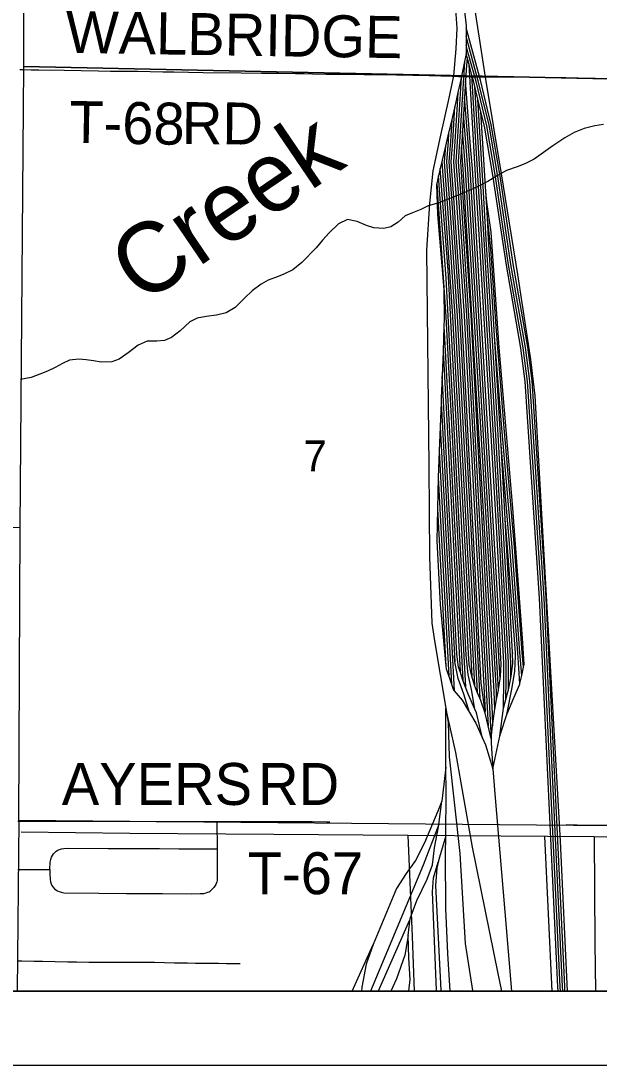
# Model space of a CAD drawing. Extents: x 0 to 40.2, y 0 to 22.
# Drawn here: x 2.953 to 3.735, y 14 to 15.414 of the extents above; entities that cross this region are included whole.
import ezdxf

# ---------------------------------------------------------------- set-up
doc = ezdxf.new("R2010")
doc.units = 0
for name, color, linetype in [('GM_X_Adjacent_County', 7, 'Continuous'), ('GM_X_City_Street', 7, 'Continuous'), ('GM_X_Corporation', 7, 'Continuous'), ('GM_X_County_Road_Text', 7, 'Continuous'), ('GM_X_Major_River', 7, 'Continuous'), ('GM_X_Minor_Lake', 7, 'Continuous'), ('GM_X_Minor_River', 7, 'Continuous'), ('GM_X_Rail_Line', 7, 'Continuous'), ('GM_X_Township_Road', 7, 'Continuous')]:
    doc.layers.add(name, color=color, linetype=linetype)

msp = doc.modelspace()

# ---------------------------------------------------------------- linework, layer by layer
at = {"layer": 'GM_X_Adjacent_County'}
for p, q in [((2.1, 14.1), (8.9, 14.1)), ((2, 14), (9, 14))]:
    msp.add_line(p, q, dxfattribs=at)
at = {"layer": 'GM_X_Corporation'}
for points in [[(2.1, 17.4265), (2.1, 14.1), (8.7736, 14.1)], [(2.9469, 14.1), (8.7736, 14.1)]]:
    msp.add_lwpolyline(points, dxfattribs=at)
for points in [[(2.955, 16.2539), (3.7456, 16.2537), (3.7481, 15.3357), (2.9569, 15.3522), (2.9567, 15.7585)], [(2.1, 15.7644), (2.1, 14.7371), (2.9519, 14.728), (2.9569, 15.3522), (2.9567, 15.7585)], [(2.9569, 15.3522), (3.7481, 15.3357), (3.751, 14.324), (2.9499, 14.3312), (2.9519, 14.728)], [(2.9479, 14.1), (3.7545, 14.1), (3.751, 14.324), (2.9499, 14.3312)]]:
    msp.add_lwpolyline(points, close=True, dxfattribs=at)
at = {"layer": 'GM_X_Major_River'}
for p, q in [((3.5554, 15.4044), (3.5554, 15.3927)), ((3.5554, 15.3927), (3.5554, 15.381)), ((3.5554, 15.381), (3.5554, 15.3694)), ((3.5533, 15.3591), (3.5488, 15.3368)), ((3.5554, 15.3694), (3.5533, 15.3591)), ((3.5567, 15.3644), (3.5554, 15.3694)), ((3.5594, 15.3549), (3.5567, 15.3644)), ((3.5633, 15.3405), (3.5594, 15.3549)), ((3.5547, 15.3328), (3.5533, 15.3107)), ((3.5444, 15.3169), (3.5401, 15.2981)), ((3.5715, 15.3081), (3.5674, 15.3252)), ((3.5756, 15.291), (3.5715, 15.3081)), ((3.5519, 15.2881), (3.5506, 15.2652)), ((3.5359, 15.28), (3.5317, 15.2625)), ((3.5317, 15.2625), (3.5275, 15.2444)), ((3.5275, 15.2444), (3.523, 15.2253)), ((3.518, 15.204), (3.5156, 15.1938)), ((3.5203, 15.2142), (3.518, 15.204)), ((3.5842, 15.1473), (3.5821, 15.1829)), ((3.5255, 15.0007), (3.5242, 14.9662)), ((3.5255, 15.0007), (3.5509, 14.5212)), ((3.5242, 14.9662), (3.523, 14.9335)), ((3.5242, 14.9662), (3.5472, 14.5328)), ((3.5216, 14.8974), (3.5202, 14.8644)), ((3.5216, 14.8974), (3.54, 14.5462)), ((3.5202, 14.8644), (3.5189, 14.8315)), ((3.5202, 14.8644), (3.5392, 14.5068)), ((3.6083, 14.7396), (3.6027, 14.8394)), ((3.5189, 14.8315), (3.5356, 14.5157)), ((3.5177, 14.7959), (3.5168, 14.7533)), ((3.5177, 14.7959), (3.5319, 14.5265)), ((3.5168, 14.7533), (3.5281, 14.5403)), ((3.54, 14.5462), (3.5397, 14.5551)), ((3.6183, 14.5587), (3.6185, 14.558)), ((3.6307, 14.5277), (3.633, 14.5388)), ((3.5319, 14.5265), (3.5356, 14.5157)), ((3.5668, 14.5145), (3.563, 14.5268)), ((3.6127, 14.5083), (3.616, 14.524)), ((3.6284, 14.5167), (3.6307, 14.5277)), ((3.5545, 14.512), (3.5509, 14.5212)), ((3.5968, 14.495), (3.5994, 14.5077)), ((3.574, 14.4968), (3.5704, 14.505)), ((3.5943, 14.4821), (3.5968, 14.495)), ((3.6061, 14.4834), (3.6094, 14.4952)), ((3.5914, 14.4594), (3.5943, 14.4821)), ((3.6013, 14.4454), (3.6061, 14.4834)), ((3.5814, 14.4765), (3.5811, 14.4788)), ((3.5852, 14.4596), (3.5814, 14.4765)), ((3.5892, 14.4416), (3.5852, 14.4596)), ((3.5892, 14.4416), (3.5914, 14.4594)), ((3.5916, 14.4014), (3.6013, 14.4454)), ((3.528, 14.4035), (3.5226, 14.3572)), ((3.5187, 14.3259), (3.5226, 14.3572)), ((3.4782, 14.1952), (3.4366, 14.1)), ((3.4014, 14.1), (3.4295, 14.1632))]:
    msp.add_line(p, q, dxfattribs=at)
for points in [[(3.6927, 14.1), (3.6831, 14.3032), (3.6569, 14.7625), (3.6489, 14.9063), (3.6429, 14.9554), (3.6256, 15.0707), (3.6032, 15.2068), (3.5819, 15.338), (3.564, 15.4524), (3.5427, 15.5845), (3.5383, 15.6139)], [(3.5416, 15.5186), (3.5488, 15.4673), (3.5554, 15.4075), (3.5554, 15.4044)], [(3.5405, 15.4359), (3.5431, 15.4041), (3.5414, 15.376), (3.5386, 15.3395), (3.5317, 15.3074), (3.521, 15.2593), (3.5103, 15.2111), (3.506, 15.1669), (3.5017, 15.1033), (3.5049, 14.8112), (3.5059, 14.6883), (3.509, 14.5984), (3.5126, 14.5743), (3.528, 14.4832)], [(3.6893, 14.1), (3.689, 14.1065), (3.664, 14.6327), (3.6449, 14.9264), (3.6389, 14.9723), (3.6192, 15.0848), (3.6014, 15.2038), (3.5895, 15.2733), (3.5749, 15.3336), (3.5644, 15.3718), (3.5554, 15.4044)], [(3.6862, 14.1), (3.6859, 14.1064), (3.6609, 14.6325), (3.6418, 14.9261), (3.6358, 14.9718), (3.6161, 15.0843), (3.5983, 15.2033), (3.5865, 15.2726), (3.5719, 15.3328), (3.5614, 15.371), (3.5554, 15.3927)], [(3.6831, 14.1), (3.6828, 14.1062), (3.6578, 14.6323), (3.6387, 14.9258), (3.6328, 14.9713), (3.613, 15.0838), (3.5953, 15.2028), (3.5834, 15.272), (3.5689, 15.332), (3.5584, 15.3702), (3.5554, 15.381)], [(3.5533, 15.3591), (3.5495, 15.3005), (3.5466, 15.2502), (3.5446, 15.2233), (3.5481, 15.175), (3.5589, 15.0152), (3.5875, 14.4758), (3.5892, 14.4416)], [(3.5567, 15.3644), (3.5557, 15.3478), (3.5547, 15.3328)], [(3.6061, 14.4834), (3.6067, 14.5219), (3.6067, 14.5449), (3.5969, 14.7212), (3.5899, 14.8451), (3.5791, 15.026), (3.5735, 15.1177), (3.5692, 15.1895), (3.5594, 15.3549)], [(3.5488, 15.3368), (3.5464, 15.3007), (3.5435, 15.2504), (3.5415, 15.2233), (3.545, 15.1747), (3.5558, 15.015), (3.5844, 14.4757), (3.5852, 14.4596)], [(3.5488, 15.3368), (3.5475, 15.3306), (3.5444, 15.3169)], [(3.6016, 14.5229), (3.6022, 14.5268), (3.6031, 14.5429), (3.6022, 14.5591), (3.6012, 14.5828), (3.5639, 15.2139), (3.5616, 15.2439), (3.5547, 15.3328)], [(3.6094, 14.4952), (3.6098, 14.5219), (3.6098, 14.545), (3.6, 14.7213), (3.593, 14.8453), (3.5822, 15.0261), (3.5766, 15.1179), (3.5723, 15.1897), (3.5633, 15.3405)], [(3.5674, 15.3252), (3.5659, 15.3312), (3.5633, 15.3405)], [(3.5444, 15.3169), (3.5433, 15.3009), (3.5404, 15.2506), (3.5384, 15.2233), (3.5419, 15.1745), (3.5527, 15.0148), (3.5811, 14.4788)], [(3.6127, 14.5083), (3.6129, 14.5218), (3.6129, 14.5451), (3.6031, 14.7215), (3.5961, 14.8455), (3.5853, 15.0263), (3.5797, 15.1181), (3.5754, 15.1899), (3.5674, 15.3252)], [(3.5533, 15.3107), (3.5526, 15.3003), (3.5519, 15.2881)], [(3.6016, 14.5229), (3.5608, 15.2137), (3.5585, 15.2437), (3.5533, 15.3107)], [(3.616, 14.524), (3.616, 14.5452), (3.6062, 14.7217), (3.5993, 14.8457), (3.5884, 15.0265), (3.5828, 15.1183), (3.5785, 15.1901), (3.5715, 15.3081)], [(3.5811, 14.4788), (3.5768, 14.511), (3.576, 14.5172), (3.5496, 15.0146), (3.5388, 15.1743), (3.5353, 15.2233), (3.5373, 15.2508), (3.5401, 15.2981)], [(3.5401, 15.2981), (3.537, 15.2845), (3.5359, 15.28)], [(3.5994, 14.5077), (3.5577, 15.2135), (3.5554, 15.2435), (3.5519, 15.2881)], [(3.68, 14.1), (3.6797, 14.1061), (3.6547, 14.6322), (3.6356, 14.9255), (3.6297, 14.9708), (3.61, 15.0833), (3.5922, 15.2023), (3.5804, 15.2714), (3.5756, 15.291)], [(3.5821, 15.1829), (3.5816, 15.1903), (3.5756, 15.291)], [(3.5359, 15.28), (3.5342, 15.251), (3.5322, 15.2233), (3.5357, 15.1741), (3.5465, 15.0144), (3.574, 14.4968)], [(3.5317, 15.2625), (3.5311, 15.2512), (3.529, 15.2233), (3.5326, 15.1739), (3.5434, 15.0142), (3.5704, 14.505)], [(3.5506, 15.2652), (3.5497, 15.25), (3.5492, 15.243)], [(3.5968, 14.495), (3.5964, 14.5059), (3.5546, 15.2133), (3.5523, 15.2432), (3.5506, 15.2652)], [(3.5275, 15.2444), (3.5259, 15.2233), (3.5295, 15.1737), (3.5403, 15.014), (3.5668, 14.5145)], [(3.5492, 15.243), (3.5477, 15.2233), (3.5512, 15.1752), (3.562, 15.0153), (3.5906, 14.476), (3.5914, 14.4594)], [(3.5943, 14.4821), (3.5933, 14.5058), (3.5515, 15.2131), (3.5492, 15.243)], [(3.523, 15.2253), (3.5225, 15.2234), (3.5203, 15.2142)], [(3.523, 15.2253), (3.5228, 15.2233), (3.5264, 15.1734), (3.5372, 15.0138), (3.563, 14.5268)], [(3.5671, 14.4819), (3.5627, 14.5087), (3.5581, 14.5291), (3.5555, 14.5551), (3.5284, 15.0657), (3.5202, 15.173), (3.518, 15.204)], [(3.563, 14.5268), (3.563, 14.5268), (3.5597, 14.5423), (3.5588, 14.5574), (3.5312, 15.0766), (3.5233, 15.1732), (3.5203, 15.2142)], [(3.5156, 15.1938), (3.5153, 15.1925), (3.5166, 15.1517), (3.5251, 15.0504), (3.5258, 15.0096), (3.5255, 15.0007)], [(3.5156, 15.1938), (3.5171, 15.1728), (3.5279, 15.0133), (3.5545, 14.512)], [(3.633, 14.5388), (3.6339, 14.5431), (3.6324, 14.5718), (3.6188, 14.7542), (3.6001, 14.9718), (3.5892, 15.1279), (3.5833, 15.1685), (3.5821, 15.1829)], [(3.633, 14.5388), (3.6315, 14.5588), (3.6209, 14.7015), (3.6065, 14.8679), (3.596, 15.0003), (3.589, 15.1054), (3.5842, 15.1473)], [(3.5938, 14.9877), (3.5915, 15.0267), (3.5859, 15.1184), (3.5842, 15.1473)], [(3.6307, 14.5277), (3.6284, 14.5585), (3.6178, 14.7013), (3.6034, 14.8677), (3.5938, 14.9877)], [(3.6027, 14.8394), (3.6024, 14.8458), (3.5938, 14.9877)], [(3.523, 14.9335), (3.5218, 14.9031), (3.5216, 14.8974)], [(3.5472, 14.5328), (3.5453, 14.5387), (3.543, 14.5564), (3.523, 14.9335)], [(3.6284, 14.5167), (3.6253, 14.5583), (3.6147, 14.701), (3.6027, 14.8394)], [(3.5189, 14.8315), (3.5179, 14.8078), (3.5177, 14.7959)], [(3.5168, 14.7533), (3.5159, 14.7098), (3.5205, 14.6236), (3.5281, 14.5403)], [(3.6105, 14.4748), (3.6176, 14.5114), (3.6212, 14.5334), (3.6225, 14.5531), (3.6222, 14.5581), (3.6116, 14.7008), (3.6083, 14.7396)], [(3.6183, 14.5587), (3.6093, 14.7218), (3.6083, 14.7396)], [(3.616, 14.524), (3.6166, 14.5268), (3.6186, 14.5439), (3.6183, 14.5587)], [(3.5281, 14.5403), (3.5284, 14.5368), (3.5319, 14.5265)], [(3.56, 14.4775), (3.5525, 14.5025), (3.5446, 14.5235), (3.54, 14.5462)], [(3.5509, 14.5212), (3.5509, 14.5212), (3.5472, 14.5328)], [(3.5994, 14.5077), (3.5995, 14.5084), (3.6016, 14.5229)], [(3.5356, 14.5157), (3.5383, 14.5079), (3.5392, 14.5068)], [(3.5671, 14.4819), (3.5588, 14.5012), (3.5545, 14.512)], [(3.5704, 14.505), (3.568, 14.5107), (3.5668, 14.5145)], [(3.6094, 14.4952), (3.6117, 14.5035), (3.6127, 14.5083)], [(3.6105, 14.4748), (3.6201, 14.4973), (3.6282, 14.5158), (3.6284, 14.5167)], [(3.5392, 14.5068), (3.5501, 14.4941), (3.56, 14.4775)], [(3.5814, 14.4765), (3.5752, 14.4939), (3.574, 14.4968)], [(3.528, 14.4035), (3.5278, 14.4117), (3.528, 14.4832)], [(3.6036, 14.1), (3.5989, 14.124), (3.564, 14.2953), (3.5417, 14.4233), (3.528, 14.4832)], [(3.528, 14.4832), (3.5313, 14.464), (3.5325, 14.4175), (3.5469, 14.2864), (3.5542, 14.1648), (3.564, 14.1012), (3.5642, 14.1)], [(3.5776, 14.4427), (3.5693, 14.4768), (3.5671, 14.4819)], [(3.56, 14.4775), (3.5685, 14.4632), (3.5776, 14.4427)], [(3.6013, 14.4454), (3.6021, 14.4487), (3.6105, 14.4748)], [(3.5776, 14.4427), (3.5817, 14.4336), (3.5916, 14.4014)], [(3.5892, 14.4416), (3.5895, 14.4361), (3.5916, 14.4014)], [(3.5278, 14.3105), (3.5285, 14.3683), (3.528, 14.4035)], [(3.5916, 14.4014), (3.5942, 14.3672), (3.608, 14.2074), (3.6171, 14.1)], [(3.5226, 14.3572), (3.517, 14.3437), (3.4989, 14.3009), (3.4871, 14.2769), (3.4743, 14.2595), (3.4611, 14.2391), (3.4295, 14.1632)], [(3.5187, 14.3259), (3.4973, 14.2707), (3.4262, 14.1)], [(3.4769, 14.1753), (3.4798, 14.1987), (3.4887, 14.2227), (3.5029, 14.2516), (3.5098, 14.271), (3.5127, 14.2944), (3.5183, 14.3226), (3.5187, 14.3259)], [(3.5278, 14.3105), (3.5193, 14.2815), (3.5178, 14.2746)], [(3.5339, 14.1), (3.5305, 14.151), (3.5278, 14.2122), (3.5275, 14.2858), (3.5278, 14.3105)], [(3.5154, 14.1017), (3.5098, 14.2348), (3.5111, 14.2536), (3.5178, 14.2746)], [(3.5178, 14.2746), (3.516, 14.2667), (3.514, 14.2434), (3.5213, 14.1017)], [(3.4769, 14.1753), (3.4726, 14.1487), (3.4611, 14.1168), (3.4537, 14.1)], [(3.4778, 14.1), (3.4795, 14.1161), (3.4779, 14.1451), (3.4769, 14.1753)], [(3.4295, 14.1632), (3.4203, 14.1369), (3.4144, 14.1056), (3.4139, 14.1)]]:
    msp.add_lwpolyline(points, dxfattribs=at)
at = {"layer": 'GM_X_Minor_Lake'}
msp.add_line((3.6615, 14.3094), (3.6717, 14.1), dxfattribs=at)
for points in [[(3.7413, 15.2739), (3.7295, 15.2718), (3.7151, 15.2682), (3.7018, 15.263), (3.6893, 15.2556), (3.6729, 15.2448), (3.6477, 15.2269), (3.6348, 15.2202), (3.6245, 15.2165), (3.6101, 15.2114), (3.5979, 15.2044), (3.585, 15.1965), (3.5705, 15.1895), (3.5557, 15.1825), (3.5417, 15.1766), (3.531, 15.1726), (3.5185, 15.1678), (3.5041, 15.1634), (3.4942, 15.1586), (3.4828, 15.1542), (3.4729, 15.1498), (3.4634, 15.1415), (3.4535, 15.1352), (3.444, 15.1327), (3.4304, 15.1336), (3.4206, 15.1368), (3.4078, 15.1422), (3.3947, 15.145), (3.3825, 15.1391), (3.3699, 15.1271), (3.3611, 15.117), (3.3526, 15.1069), (3.3331, 15.087)], [(3.3331, 15.087), (3.3209, 15.0769), (3.3076, 15.0706), (3.2973, 15.0666), (3.2874, 15.0629), (3.2779, 15.0573), (3.2657, 15.0484), (3.2554, 15.0386), (3.2428, 15.0259), (3.2306, 15.0185), (3.2177, 15.0156), (3.2037, 15.0139), (3.1916, 15.0114), (3.1813, 15.0065), (3.1683, 14.9942), (3.1568, 14.9852), (3.147, 14.9812), (3.1368, 14.9805), (3.1239, 14.9803), (3.1114, 14.9748), (3.098, 14.9647), (3.0858, 14.9561), (3.0759, 14.9521), (3.0612, 14.9519), (3.051, 14.9535), (3.0412, 14.9548), (3.031, 14.9561), (3.0186, 14.9547), (3.0091, 14.9499), (2.9992, 14.9447), (2.9889, 14.9395), (2.9786, 14.9355), (2.9665, 14.9311), (2.9521, 14.9282)], [(4.2967, 14.2987), (4.1649, 14.3008), (4.0478, 14.3022), (3.9387, 14.3044), (3.8325, 14.3065), (3.7287, 14.3089), (3.4764, 14.3109), (3.295, 14.3121), (3.1001, 14.3138), (2.9532, 14.3156)], [(3.4764, 14.3109), (3.4825, 14.1742), (3.4852, 14.1)], [(3.7287, 14.3089), (3.7295, 14.1658), (3.7306, 14.1)]]:
    msp.add_lwpolyline(points, dxfattribs=at)
at = {"layer": 'GM_X_Rail_Line'}
msp.add_line((3.2182, 14.33), (3.2184, 14.2927), dxfattribs=at)
for points in [[(2.9515, 15.3481), (2.9557, 15.348), (2.9665, 15.3479), (2.9771, 15.3478), (3.0115, 15.3471), (3.0572, 15.3462), (3.074, 15.346), (3.1107, 15.3457), (3.1449, 15.3452), (3.1598, 15.3449), (3.1995, 15.3442), (3.2511, 15.3435), (3.2791, 15.3432), (3.2878, 15.3431), (3.3015, 15.3431), (3.3245, 15.3429), (3.3363, 15.3426), (3.3475, 15.3423), (3.3661, 15.342), (3.3773, 15.3419), (3.3916, 15.3418), (3.4174, 15.3415), (3.4288, 15.3414), (3.461, 15.3408), (3.5053, 15.34), (3.5214, 15.3397), (3.5368, 15.3391), (3.5451, 15.3389), (3.5572, 15.3385), (3.5642, 15.3384), (3.5742, 15.3384), (3.5845, 15.3384)], [(3.5845, 15.3384), (3.5866, 15.3384), (3.5978, 15.3384), (3.6351, 15.3381), (3.6612, 15.3377), (3.6904, 15.3372), (3.7072, 15.3369), (3.7308, 15.3364), (3.7443, 15.3356)], [(2.9488, 14.3304), (2.9566, 14.3303), (2.9883, 14.3302), (3.0442, 14.3302), (3.0921, 14.3302), (3.1357, 14.3301), (3.1612, 14.33), (3.2182, 14.33)], [(3.2182, 14.33), (3.2427, 14.33), (3.2663, 14.3299), (3.3042, 14.3299), (3.3471, 14.3298), (3.3671, 14.3296), (3.3708, 14.3296)], [(3.6911, 14.3257), (3.706, 14.3254), (3.7271, 14.3251), (3.755, 14.3248), (3.7568, 14.3248)], [(2.992, 14.2648), (2.9924, 14.2746), (2.9932, 14.2784), (2.9943, 14.2815), (2.9954, 14.2838), (2.9969, 14.286), (2.9986, 14.288), (3.0006, 14.2897), (3.0028, 14.291), (3.0052, 14.2921), (3.0077, 14.2929), (3.0109, 14.2933), (3.0178, 14.2936), (3.0707, 14.2934), (3.1136, 14.2933), (3.1404, 14.2932), (3.1665, 14.293), (3.2107, 14.2928), (3.2184, 14.2927)], [(3.2184, 14.2927), (3.2186, 14.2537), (3.2183, 14.2502), (3.2179, 14.248), (3.2173, 14.2461), (3.2166, 14.2446), (3.2158, 14.2432), (3.215, 14.242), (3.214, 14.2405), (3.2127, 14.239), (3.2109, 14.2372), (3.2089, 14.2356)], [(2.9487, 14.2648), (2.957, 14.2648), (2.9695, 14.2648), (2.992, 14.2648)], [(2.992, 14.2648), (2.9919, 14.259), (2.9925, 14.2517), (2.993, 14.248), (2.9937, 14.2456), (2.9948, 14.2434), (2.9961, 14.2413), (2.9982, 14.2389), (3.0001, 14.2373), (3.0022, 14.236), (3.0044, 14.235), (3.0074, 14.2341), (3.0111, 14.2335), (3.0583, 14.2327), (3.0956, 14.2326), (3.1446, 14.2323), (3.1832, 14.2321), (3.1956, 14.2322), (3.2006, 14.2326), (3.2036, 14.2332), (3.2059, 14.234), (3.2075, 14.2347), (3.2089, 14.2356)], [(2.9477, 14.141), (2.9541, 14.141), (2.9707, 14.1407), (2.9821, 14.1406), (2.999, 14.1402), (3.0162, 14.1399), (3.0212, 14.1398), (3.0282, 14.1397), (3.0446, 14.1396), (3.0582, 14.1396), (3.0637, 14.1396), (3.0705, 14.1395), (3.0798, 14.1394), (3.0861, 14.1394), (3.0963, 14.1394), (3.1056, 14.1394), (3.1214, 14.1394), (3.1334, 14.1392), (3.1608, 14.1387), (3.1665, 14.1387), (3.1728, 14.1385), (3.1785, 14.1383), (3.1891, 14.1382), (3.2042, 14.138), (3.2203, 14.1379), (3.2313, 14.1378), (3.245, 14.1377), (3.2498, 14.1377)]]:
    msp.add_lwpolyline(points, dxfattribs=at)
at = {"layer": 'GM_X_Township_Road'}
msp.add_lwpolyline([(2.1, 20.9), (8.9, 20.9), (8.9, 14.1), (2.1, 14.1)], close=True, dxfattribs=at)

# ---------------------------------------------------------------- texts
at = {"layer": 'GM_X_City_Street'}
msp.add_text('7', height=0.0419, rotation=0, dxfattribs=at).set_placement((3.3356, 14.8039))
at = {"layer": 'GM_X_County_Road_Text'}
for s, rotation, p in [('WALBRIDGE', 359.0837, (3.013, 15.3707)), ('T-68', 358.9473, (3.0178, 15.2489)), ('RD', 359.4936, (3.1704, 15.2473)), ('AYERS', 0, (3.0081, 14.3523)), ('RD', 0, (3.2739, 14.3523)), ('T-67', 0, (3.2598, 14.2314))]:
    msp.add_text(s, height=0.05682, rotation=rotation, dxfattribs=at).set_placement(p)
at = {"layer": 'GM_X_Minor_River'}
msp.add_text('Creek', height=0.09476, rotation=34.1957, dxfattribs=at).set_placement((3.1165, 15.0284))

doc.saveas('drawing.dxf')
